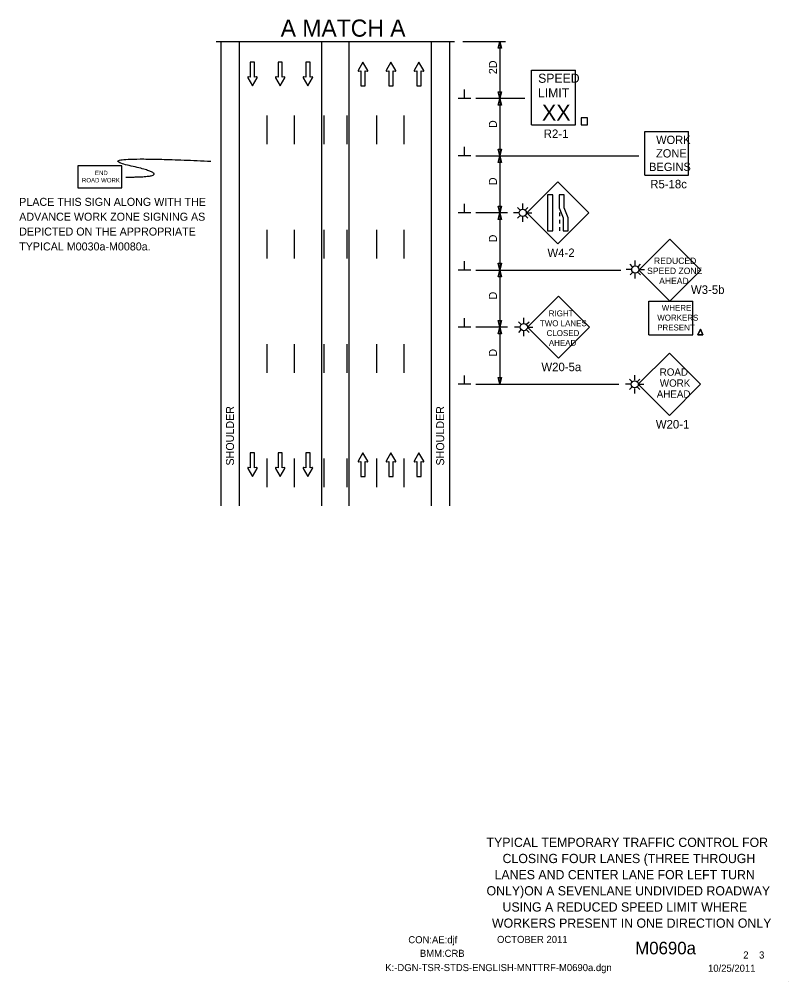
# Model space of a CAD drawing. Extents: x 16038 to 19504, y 5710 to 8321.
# Drawn here: x 17779 to 18453, y 5924 to 6766 of the extents above; entities that cross this region are included whole.
import ezdxf

# ---------------------------------------------------------------- set-up
doc = ezdxf.new("R2010")
doc.units = 0
for name, color, linetype in [('ALI_LEGAL_EX', 7, 'Continuous'), ('BORDER', 7, 'Continuous'), ('BORDER_SIGNAL_WO', 7, 'Continuous'), ('MT_SCRATCH_LEVEL_E', 7, 'Continuous'), ('PAVT_EDGE_EX', 7, 'Continuous'), ('TRAFFIC_SIGNS_PR', 7, 'Continuous'), ('TYPICAL_TEXT_DIMEN_PR', 7, 'Continuous')]:
    doc.layers.add(name, color=color, linetype=linetype)

msp = doc.modelspace()

# ---------------------------------------------------------------- linework, layer by layer
at = {"layer": 'ALI_LEGAL_EX'}
for points in [[(17995.77, 6682.18), (17995.77, 6657.18)], [(18019.77, 6682.18), (18019.77, 6657.18)], [(18045.77, 6682.18), (18045.77, 6657.18)], [(18065.77, 6682.18), (18065.77, 6657.18)], [(18091.77, 6682.18), (18091.77, 6657.18)], [(18115.77, 6682.18), (18115.77, 6657.18)], [(17995.77, 6582.18), (17995.77, 6557.18)], [(18019.77, 6582.18), (18019.77, 6557.18)], [(18045.77, 6582.18), (18045.77, 6557.18)], [(18065.77, 6582.18), (18065.77, 6557.18)], [(18091.77, 6582.18), (18091.77, 6557.18)], [(18115.77, 6582.18), (18115.77, 6557.18)], [(17995.77, 6482.18), (17995.77, 6457.18)], [(18019.77, 6482.18), (18019.77, 6457.18)], [(18045.77, 6482.18), (18045.77, 6457.18)], [(18065.77, 6482.18), (18065.77, 6457.18)], [(18091.77, 6482.18), (18091.77, 6457.18)], [(18115.77, 6482.18), (18115.77, 6457.18)], [(17995.77, 6382.18), (17995.77, 6357.18)], [(18019.77, 6382.18), (18019.77, 6357.18)], [(18045.77, 6382.18), (18045.77, 6357.18)], [(18065.77, 6382.18), (18065.77, 6357.18)], [(18091.77, 6382.18), (18091.77, 6357.18)], [(18115.77, 6382.18), (18115.77, 6357.18)]]:
    msp.add_lwpolyline(points, dxfattribs=at)
at = {"layer": 'BORDER'}
for p, q in [((18318.25, 6011.25), (18318.25, 6011.25)), ((18452.55, 5924.4), (18452.55, 5924.4))]:
    msp.add_line(p, q, dxfattribs=at)
at = {"layer": 'MT_SCRATCH_LEVEL_E'}
for p, q in [((17985.18, 6728.89), (17981.44, 6728.89)), ((17981.44, 6728.89), (17981.44, 6715.63)), ((17985.18, 6728.89), (17981.44, 6728.89)), ((17981.44, 6728.89), (17981.44, 6715.63)), ((17985.18, 6715.63), (17985.18, 6728.89)), ((17985.18, 6715.63), (17985.18, 6728.89)), ((18009.44, 6728.89), (18005.69, 6728.89)), ((18005.69, 6728.89), (18005.69, 6715.63)), ((18009.44, 6728.89), (18005.69, 6728.89)), ((18005.69, 6728.89), (18005.69, 6715.63)), ((18009.44, 6715.63), (18009.44, 6728.89)), ((18009.44, 6715.63), (18009.44, 6728.89)), ((18033.69, 6728.89), (18029.95, 6728.89)), ((18029.95, 6728.89), (18029.95, 6715.63)), ((18033.69, 6728.89), (18029.95, 6728.89)), ((18029.95, 6728.89), (18029.95, 6715.63)), ((18033.69, 6715.63), (18033.69, 6728.89)), ((18033.69, 6715.63), (18033.69, 6728.89)), ((18080.01, 6728.89), (18075.9, 6721.65)), ((18080.01, 6728.89), (18075.9, 6721.65)), ((18084.16, 6721.65), (18080.01, 6728.89)), ((18084.16, 6721.65), (18080.01, 6728.89)), ((18104.51, 6728.89), (18100.4, 6721.65)), ((18104.51, 6728.89), (18100.4, 6721.65)), ((18108.65, 6721.65), (18104.51, 6728.89)), ((18108.65, 6721.65), (18104.51, 6728.89)), ((18129, 6728.89), (18124.89, 6721.65)), ((18129, 6728.89), (18124.89, 6721.65)), ((18133.15, 6721.65), (18129, 6728.89)), ((18133.15, 6721.65), (18129, 6728.89)), ((18076.38, 6720.96), (18078.16, 6721.28)), ((18076.38, 6720.96), (18078.16, 6721.28)), ((18078.16, 6721.28), (18078.16, 6708.02)), ((18078.16, 6721.28), (18078.16, 6708.02)), ((18081.9, 6708.02), (18081.9, 6721.28)), ((18081.9, 6721.28), (18083.68, 6720.96)), ((18081.9, 6708.02), (18081.9, 6721.28)), ((18081.9, 6721.28), (18083.68, 6720.96)), ((18100.88, 6720.96), (18102.65, 6721.28)), ((18100.88, 6720.96), (18102.65, 6721.28)), ((18102.65, 6721.28), (18102.65, 6708.02)), ((18102.65, 6721.28), (18102.65, 6708.02)), ((18106.4, 6708.02), (18106.4, 6721.28)), ((18106.4, 6721.28), (18108.17, 6720.96)), ((18106.4, 6708.02), (18106.4, 6721.28)), ((18106.4, 6721.28), (18108.17, 6720.96)), ((18125.37, 6720.96), (18127.15, 6721.28)), ((18125.37, 6720.96), (18127.15, 6721.28)), ((18127.15, 6721.28), (18127.15, 6708.02)), ((18127.15, 6721.28), (18127.15, 6708.02)), ((18130.89, 6708.02), (18130.89, 6721.28)), ((18130.89, 6721.28), (18132.67, 6720.96)), ((18130.89, 6708.02), (18130.89, 6721.28)), ((18130.89, 6721.28), (18132.67, 6720.96)), ((17979.18, 6715.26), (17983.33, 6708.02)), ((17979.18, 6715.26), (17983.33, 6708.02)), ((17981.44, 6715.63), (17979.66, 6715.95)), ((17981.44, 6715.63), (17979.66, 6715.95)), ((17983.33, 6708.02), (17987.44, 6715.26)), ((17983.33, 6708.02), (17987.44, 6715.26)), ((17986.96, 6715.95), (17985.18, 6715.63)), ((17986.96, 6715.95), (17985.18, 6715.63)), ((18003.44, 6715.26), (18007.58, 6708.02)), ((18003.44, 6715.26), (18007.58, 6708.02)), ((18005.69, 6715.63), (18003.92, 6715.95)), ((18005.69, 6715.63), (18003.92, 6715.95)), ((18007.58, 6708.02), (18011.69, 6715.26)), ((18007.58, 6708.02), (18011.69, 6715.26)), ((18011.21, 6715.95), (18009.44, 6715.63)), ((18011.21, 6715.95), (18009.44, 6715.63)), ((18027.69, 6715.26), (18031.84, 6708.02)), ((18027.69, 6715.26), (18031.84, 6708.02)), ((18029.95, 6715.63), (18028.17, 6715.95)), ((18029.95, 6715.63), (18028.17, 6715.95)), ((18031.84, 6708.02), (18035.95, 6715.26)), ((18031.84, 6708.02), (18035.95, 6715.26)), ((18035.47, 6715.95), (18033.69, 6715.63)), ((18035.47, 6715.95), (18033.69, 6715.63)), ((18078.16, 6708.02), (18081.9, 6708.02)), ((18078.16, 6708.02), (18081.9, 6708.02)), ((18102.65, 6708.02), (18106.4, 6708.02)), ((18102.65, 6708.02), (18106.4, 6708.02)), ((18127.15, 6708.02), (18130.89, 6708.02)), ((18127.15, 6708.02), (18130.89, 6708.02)), ((17985.18, 6387.14), (17981.44, 6387.14)), ((17981.44, 6387.14), (17981.44, 6373.88)), ((17985.18, 6387.14), (17981.44, 6387.14)), ((17981.44, 6387.14), (17981.44, 6373.88)), ((17985.18, 6373.88), (17985.18, 6387.14)), ((17985.18, 6373.88), (17985.18, 6387.14)), ((18009.44, 6387.14), (18005.69, 6387.14)), ((18005.69, 6387.14), (18005.69, 6373.88)), ((18009.44, 6387.14), (18005.69, 6387.14)), ((18005.69, 6387.14), (18005.69, 6373.88)), ((18009.44, 6373.88), (18009.44, 6387.14)), ((18009.44, 6373.88), (18009.44, 6387.14)), ((18033.69, 6387.14), (18029.95, 6387.14)), ((18029.95, 6387.14), (18029.95, 6373.88)), ((18033.69, 6387.14), (18029.95, 6387.14)), ((18029.95, 6387.14), (18029.95, 6373.88)), ((18033.69, 6373.88), (18033.69, 6387.14)), ((18033.69, 6373.88), (18033.69, 6387.14)), ((18080.01, 6387.14), (18075.9, 6379.9)), ((18080.01, 6387.14), (18075.9, 6379.9)), ((18084.16, 6379.9), (18080.01, 6387.14)), ((18084.16, 6379.9), (18080.01, 6387.14)), ((18104.51, 6387.14), (18100.4, 6379.9)), ((18104.51, 6387.14), (18100.4, 6379.9)), ((18108.65, 6379.9), (18104.51, 6387.14)), ((18108.65, 6379.9), (18104.51, 6387.14)), ((18129, 6387.14), (18124.89, 6379.9)), ((18129, 6387.14), (18124.89, 6379.9)), ((18133.15, 6379.9), (18129, 6387.14)), ((18133.15, 6379.9), (18129, 6387.14)), ((17981.44, 6373.88), (17979.66, 6374.2)), ((17981.44, 6373.88), (17979.66, 6374.2)), ((17986.96, 6374.2), (17985.18, 6373.88)), ((17986.96, 6374.2), (17985.18, 6373.88)), ((18005.69, 6373.88), (18003.92, 6374.2)), ((18005.69, 6373.88), (18003.92, 6374.2)), ((18011.21, 6374.2), (18009.44, 6373.88)), ((18011.21, 6374.2), (18009.44, 6373.88)), ((18029.95, 6373.88), (18028.17, 6374.2)), ((18029.95, 6373.88), (18028.17, 6374.2)), ((18035.47, 6374.2), (18033.69, 6373.88)), ((18035.47, 6374.2), (18033.69, 6373.88)), ((18076.38, 6379.22), (18078.16, 6379.53)), ((18076.38, 6379.22), (18078.16, 6379.53)), ((18078.16, 6379.53), (18078.16, 6366.27)), ((18078.16, 6379.53), (18078.16, 6366.27)), ((18081.9, 6366.27), (18081.9, 6379.53)), ((18081.9, 6379.53), (18083.68, 6379.22)), ((18081.9, 6366.27), (18081.9, 6379.53)), ((18081.9, 6379.53), (18083.68, 6379.22)), ((18100.88, 6379.22), (18102.65, 6379.53)), ((18100.88, 6379.22), (18102.65, 6379.53)), ((18102.65, 6379.53), (18102.65, 6366.27)), ((18102.65, 6379.53), (18102.65, 6366.27)), ((18106.4, 6366.27), (18106.4, 6379.53)), ((18106.4, 6379.53), (18108.17, 6379.22)), ((18106.4, 6366.27), (18106.4, 6379.53)), ((18106.4, 6379.53), (18108.17, 6379.22)), ((18125.37, 6379.22), (18127.15, 6379.53)), ((18125.37, 6379.22), (18127.15, 6379.53)), ((18127.15, 6379.53), (18127.15, 6366.27)), ((18127.15, 6379.53), (18127.15, 6366.27)), ((18130.89, 6366.27), (18130.89, 6379.53)), ((18130.89, 6379.53), (18132.67, 6379.22)), ((18130.89, 6366.27), (18130.89, 6379.53)), ((18130.89, 6379.53), (18132.67, 6379.22)), ((17979.18, 6373.51), (17983.33, 6366.27)), ((17979.18, 6373.51), (17983.33, 6366.27)), ((17983.33, 6366.27), (17987.44, 6373.51)), ((17983.33, 6366.27), (17987.44, 6373.51)), ((18003.44, 6373.51), (18007.58, 6366.27)), ((18003.44, 6373.51), (18007.58, 6366.27)), ((18007.58, 6366.27), (18011.69, 6373.51)), ((18007.58, 6366.27), (18011.69, 6373.51)), ((18027.69, 6373.51), (18031.84, 6366.27)), ((18027.69, 6373.51), (18031.84, 6366.27)), ((18031.84, 6366.27), (18035.95, 6373.51)), ((18031.84, 6366.27), (18035.95, 6373.51)), ((18078.16, 6366.27), (18081.9, 6366.27)), ((18078.16, 6366.27), (18081.9, 6366.27)), ((18102.65, 6366.27), (18106.4, 6366.27)), ((18102.65, 6366.27), (18106.4, 6366.27)), ((18127.15, 6366.27), (18130.89, 6366.27)), ((18127.15, 6366.27), (18130.89, 6366.27))]:
    msp.add_line(p, q, dxfattribs=at)
for centre, start, end in [((18076.31, 6721.42), 150.42484, 279.96381), ((18076.31, 6721.42), 150.42484, 279.96381), ((18083.75, 6721.42), 260.03619, 29.77312), ((18083.75, 6721.42), 260.03619, 29.77312), ((18100.8, 6721.42), 150.42484, 279.96381), ((18100.8, 6721.42), 150.42484, 279.96381), ((18108.24, 6721.42), 260.03619, 29.77312), ((18108.24, 6721.42), 260.03619, 29.77312), ((18125.3, 6721.42), 150.42484, 279.96381), ((18125.3, 6721.42), 150.42484, 279.96381), ((18132.74, 6721.42), 260.03619, 29.77312), ((18132.74, 6721.42), 260.03619, 29.77312), ((17979.59, 6715.49), 80.03619, 209.77312), ((17979.59, 6715.49), 80.03619, 209.77312), ((17987.03, 6715.49), 330.42484, 99.96381), ((17987.03, 6715.49), 330.42484, 99.96381), ((18003.85, 6715.49), 80.03619, 209.77312), ((18003.85, 6715.49), 80.03619, 209.77312), ((18011.29, 6715.49), 330.42484, 99.96381), ((18011.29, 6715.49), 330.42484, 99.96381), ((18028.1, 6715.49), 80.03619, 209.77312), ((18028.1, 6715.49), 80.03619, 209.77312), ((18035.54, 6715.49), 330.42484, 99.96381), ((18035.54, 6715.49), 330.42484, 99.96381), ((17979.59, 6373.74), 80.03619, 209.77312), ((17979.59, 6373.74), 80.03619, 209.77312), ((17987.03, 6373.74), 330.42484, 99.96381), ((17987.03, 6373.74), 330.42484, 99.96381), ((18003.85, 6373.74), 80.03619, 209.77312), ((18003.85, 6373.74), 80.03619, 209.77312), ((18011.29, 6373.74), 330.42484, 99.96381), ((18011.29, 6373.74), 330.42484, 99.96381), ((18028.1, 6373.74), 80.03619, 209.77312), ((18028.1, 6373.74), 80.03619, 209.77312), ((18035.54, 6373.74), 330.42484, 99.96381), ((18035.54, 6373.74), 330.42484, 99.96381), ((18076.31, 6379.67), 150.42484, 279.96381), ((18076.31, 6379.67), 150.42484, 279.96381), ((18083.75, 6379.67), 260.03619, 29.77312), ((18083.75, 6379.67), 260.03619, 29.77312), ((18100.8, 6379.67), 150.42484, 279.96381), ((18100.8, 6379.67), 150.42484, 279.96381), ((18108.24, 6379.67), 260.03619, 29.77312), ((18108.24, 6379.67), 260.03619, 29.77312), ((18125.3, 6379.67), 150.42484, 279.96381), ((18125.3, 6379.67), 150.42484, 279.96381), ((18132.74, 6379.67), 260.03619, 29.77312), ((18132.74, 6379.67), 260.03619, 29.77312)]:
    msp.add_arc(centre, 0.463, start, end, dxfattribs=at)
at = {"layer": 'PAVT_EDGE_EX'}
for p, q in [((17955.77, 6747.01), (17955.77, 6340.84)), ((17971.77, 6747.01), (17971.77, 6340.84)), ((18043.77, 6747.01), (18043.77, 6340.84)), ((18067.77, 6747.01), (18067.77, 6340.84)), ((18139.77, 6747.01), (18139.77, 6340.84)), ((18155.77, 6747.01), (18155.77, 6340.84))]:
    msp.add_line(p, q, dxfattribs=at)
at = {"layer": 'TRAFFIC_SIGNS_PR'}
for p, q in [((18227.51, 6721.93), (18265.91, 6721.93)), ((18227.51, 6673.93), (18227.51, 6721.93)), ((18265.91, 6673.93), (18265.91, 6721.93)), ((18227.51, 6673.93), (18265.91, 6673.93)), ((18326.56, 6629.9), (18326.56, 6668.3)), ((18326.56, 6668.3), (18364.96, 6668.3)), ((18364.96, 6629.9), (18364.96, 6668.3)), ((18326.56, 6629.9), (18364.96, 6629.9)), ((18250.45, 6624.09), (18223.3, 6596.94)), ((18277.61, 6596.94), (18250.45, 6624.09)), ((18217.23, 6599.58), (18215.13, 6601.69)), ((18219.75, 6600.62), (18219.75, 6605.12)), ((18222.26, 6599.58), (18224.37, 6601.69)), ((18216.59, 6597.06), (18211.76, 6597.06)), ((18217.23, 6594.55), (18215.13, 6592.44)), ((18219.75, 6589.1), (18219.75, 6593.51)), ((18222.26, 6594.55), (18224.37, 6592.44)), ((18222.9, 6597.06), (18227.78, 6597.06)), ((18223.3, 6596.94), (18250.45, 6569.78)), ((18250.45, 6569.78), (18277.61, 6596.94)), ((18252.1, 6597.43), (18252.1, 6594.23)), ((18252.1, 6591.03), (18252.1, 6587.83)), ((18252.1, 6584.63), (18252.1, 6581.43)), ((18348.56, 6574.11), (18321.41, 6546.95)), ((18375.71, 6546.95), (18348.56, 6574.11)), ((18315.77, 6549.93), (18313.66, 6552.04)), ((18318.28, 6550.97), (18318.28, 6555.48)), ((18320.8, 6549.93), (18322.9, 6552.04)), ((18315.13, 6547.42), (18310.29, 6547.42)), ((18315.77, 6544.91), (18313.66, 6542.8)), ((18318.28, 6539.45), (18318.28, 6543.86)), ((18320.8, 6544.91), (18322.9, 6542.8)), ((18321.41, 6546.95), (18348.56, 6519.8)), ((18321.44, 6547.42), (18326.32, 6547.42)), ((18348.56, 6519.8), (18375.71, 6546.95)), ((18250.98, 6524.24), (18223.83, 6497.09)), ((18278.14, 6497.09), (18250.98, 6524.24)), ((18330.11, 6519.64), (18368.51, 6519.64)), ((18330.11, 6490.32), (18330.11, 6519.64)), ((18368.51, 6490.32), (18368.51, 6519.64)), ((18218.16, 6499.61), (18216.06, 6501.71)), ((18220.68, 6500.65), (18220.68, 6505.15)), ((18223.19, 6499.61), (18225.3, 6501.71)), ((18217.52, 6497.09), (18212.69, 6497.09)), ((18218.16, 6494.58), (18216.06, 6492.47)), ((18220.68, 6489.13), (18220.68, 6493.54)), ((18223.19, 6494.58), (18225.3, 6492.47)), ((18223.83, 6497.09), (18228.71, 6497.09)), ((18223.83, 6497.09), (18250.98, 6469.94)), ((18250.98, 6469.94), (18278.14, 6497.09)), ((18330.11, 6490.32), (18368.51, 6490.32)), ((18348.1, 6474.19), (18320.91, 6447.01)), ((18375.29, 6447.01), (18348.1, 6474.19)), ((18315.25, 6449.52), (18313.14, 6451.63)), ((18317.76, 6450.56), (18317.76, 6455.07)), ((18320.27, 6449.52), (18322.38, 6451.63)), ((18314.61, 6447.01), (18309.77, 6447.01)), ((18315.25, 6444.5), (18313.14, 6442.39)), ((18317.76, 6439.04), (18317.76, 6443.45)), ((18320.27, 6444.5), (18322.38, 6442.39)), ((18320.91, 6447.01), (18325.79, 6447.01)), ((18320.91, 6447.01), (18348.1, 6419.82)), ((18348.1, 6419.82), (18375.29, 6447.01))]:
    msp.add_line(p, q, dxfattribs=at)
for points in [[(18270.93, 6673.93), (18276.52, 6673.93), (18276.52, 6680.1), (18270.93, 6680.1)], [(17830.52, 6618.92), (17868.92, 6618.92), (17868.92, 6638.12), (17830.52, 6638.12)], [(18241.56, 6612.67), (18241.56, 6581.43), (18246.05, 6581.43), (18246.05, 6612.67)], [(18251.7, 6612.67), (18251.7, 6601.49), (18255.04, 6592.61), (18255.04, 6581.43), (18259.53, 6581.43), (18259.53, 6592.61), (18256.19, 6601.49), (18256.19, 6612.67)]]:
    msp.add_lwpolyline(points, close=True, dxfattribs=at)
for points in [[(18375.26, 6495.26), (18373.03, 6490.32)], [(18373.03, 6490.32), (18375.26, 6495.26)], [(18377.5, 6490.32), (18375.26, 6495.26)], [(18375.26, 6495.26), (18377.5, 6490.32)], [(18373.03, 6490.32), (18377.5, 6490.32)], [(18377.5, 6490.32), (18373.03, 6490.32)]]:
    msp.add_lwpolyline(points, dxfattribs=at)
for centre in [(18219.75, 6597.06), (18318.28, 6547.42), (18220.68, 6497.09), (18317.76, 6447.01)]:
    msp.add_circle(centre, 3.15, dxfattribs=at)
msp.add_open_spline([(17872.52, 6628.3), (17919.75, 6628.3), (17834.73, 6647.64), (17947.03, 6642.15)], degree=2, dxfattribs=at)
at = {"layer": 'TYPICAL_TEXT_DIMEN_PR'}
for p, q in [((17951.47, 6747.01), (18160.07, 6747.01)), ((18043.77, 6747.01), (18067.77, 6747.01)), ((18167.46, 6747.01), (18204.77, 6747.01)), ((18198.2, 6741.15), (18199.77, 6747.01)), ((18199.77, 6747.01), (18201.34, 6741.15)), ((18199.77, 6747.01), (18199.77, 6697.01)), ((18199.77, 6741.15), (18198.2, 6741.15)), ((18201.34, 6741.15), (18199.77, 6741.15)), ((18168.89, 6697.01), (18168.89, 6704.79)), ((18199.77, 6697.01), (18198.2, 6702.87)), ((18198.2, 6702.87), (18199.77, 6702.87)), ((18199.77, 6702.87), (18201.34, 6702.87)), ((18201.34, 6702.87), (18199.77, 6697.01)), ((18174.52, 6697.01), (18163.27, 6697.01)), ((18221.76, 6697.01), (18178.77, 6697.01)), ((18198.2, 6691.15), (18199.77, 6697.01)), ((18199.77, 6697.01), (18201.34, 6691.15)), ((18199.77, 6697.01), (18199.77, 6647.01)), ((18199.77, 6691.15), (18198.2, 6691.15)), ((18201.34, 6691.15), (18199.77, 6691.15)), ((18168.89, 6647.01), (18168.89, 6654.79)), ((18199.77, 6647.01), (18198.2, 6652.87)), ((18198.2, 6652.87), (18199.77, 6652.87)), ((18199.77, 6652.87), (18201.34, 6652.87)), ((18201.34, 6652.87), (18199.77, 6647.01)), ((18174.52, 6647.01), (18163.27, 6647.01)), ((18178.77, 6647.01), (18321.42, 6647.01)), ((18198.2, 6641.15), (18199.77, 6647.01)), ((18199.77, 6647.01), (18199.77, 6597.01)), ((18199.77, 6647.01), (18201.34, 6641.15)), ((18199.77, 6641.15), (18198.2, 6641.15)), ((18201.34, 6641.15), (18199.77, 6641.15)), ((18168.89, 6597.01), (18168.89, 6604.79)), ((18199.77, 6597.01), (18198.2, 6602.87)), ((18198.2, 6602.87), (18199.77, 6602.87)), ((18199.77, 6602.87), (18201.34, 6602.87)), ((18201.34, 6602.87), (18199.77, 6597.01)), ((18174.52, 6597.01), (18163.27, 6597.01)), ((18206.44, 6597.01), (18178.77, 6597.01)), ((18198.2, 6591.15), (18199.77, 6597.01)), ((18199.77, 6597.01), (18201.34, 6591.15)), ((18199.77, 6597.01), (18199.77, 6547.01)), ((18199.77, 6591.15), (18198.2, 6591.15)), ((18201.34, 6591.15), (18199.77, 6591.15)), ((18168.89, 6547.01), (18168.89, 6554.79)), ((18199.77, 6547.01), (18198.2, 6552.87)), ((18198.2, 6552.87), (18199.77, 6552.87)), ((18199.77, 6552.87), (18201.34, 6552.87)), ((18201.34, 6552.87), (18199.77, 6547.01)), ((18174.52, 6547.01), (18163.27, 6547.01)), ((18178.77, 6547.01), (18305.65, 6547.01)), ((18198.2, 6541.15), (18199.77, 6547.01)), ((18199.77, 6547.01), (18201.34, 6541.15)), ((18199.77, 6547.01), (18199.77, 6497.01)), ((18199.77, 6541.15), (18198.2, 6541.15)), ((18201.34, 6541.15), (18199.77, 6541.15)), ((18168.89, 6497.01), (18168.89, 6504.79)), ((18199.77, 6497.01), (18198.2, 6502.87)), ((18198.2, 6502.87), (18199.77, 6502.87)), ((18199.77, 6502.87), (18201.34, 6502.87)), ((18201.34, 6502.87), (18199.77, 6497.01)), ((18174.52, 6497.01), (18163.27, 6497.01)), ((18206.44, 6497.01), (18178.77, 6497.01)), ((18198.2, 6491.15), (18199.77, 6497.01)), ((18199.77, 6497.01), (18201.34, 6491.15)), ((18199.77, 6497.01), (18199.77, 6447.01)), ((18199.77, 6491.15), (18198.2, 6491.15)), ((18201.34, 6491.15), (18199.77, 6491.15)), ((18168.89, 6447.01), (18168.89, 6454.79)), ((18199.77, 6447.01), (18198.2, 6452.87)), ((18198.2, 6452.87), (18199.77, 6452.87)), ((18199.77, 6452.87), (18201.34, 6452.87)), ((18201.34, 6452.87), (18199.77, 6447.01)), ((18174.52, 6447.01), (18163.27, 6447.01)), ((18178.77, 6447.01), (18303.77, 6447.01))]:
    msp.add_line(p, q, dxfattribs=at)

# ---------------------------------------------------------------- texts
at = {"layer": 'BORDER'}
for s, p in [('TYPICAL TEMPORARY TRAFFIC CONTROL FOR ', (18188.13, 6042.33)), ('CLOSING FOUR LANES (THREE THROUGH ', (18202.13, 6028.2)), ('LANES AND CENTER LANE FOR LEFT TURN ', (18195.13, 6014.06)), ('ONLY)ON A SEVENLANE UNDIVIDED ROADWAY ', (18188.13, 5999.92)), ('USING A REDUCED SPEED LIMIT WHERE ', (18202.13, 5985.79)), ('WORKERS PRESENT IN ONE DIRECTION ONLY', (18192.87, 5971.65))]:
    msp.add_text(s, height=8.066, dxfattribs=at).set_placement(p)
at = {"layer": 'BORDER_SIGNAL_WO'}
for s, height, p in [('CON:AE:djf', 6.2, (18119.69, 5958.06)), ('    OCTOBER 2011    ', 6.2, (18188.08, 5958.34)), ('    M0690a   ', 11, (18301.86, 5948.38)), ('BMM:CRB   ', 6.2, (18129.81, 5946.17)), (' 2    3 ', 6.2, (18410.45, 5944.7)), ('K:-DGN-TSR-STDS-ENGLISH-MNTTRF-M0690a.dgn        ', 6.2, (18099.55, 5933.71)), ('10/25/2011    ', 6.2, (18381.93, 5933.13))]:
    msp.add_text(s, height=height, dxfattribs=at).set_placement(p)
at = {"layer": 'TRAFFIC_SIGNS_PR'}
for s, height, p in [('SPEED', 8, (18233.28, 6710.79)), ('LIMIT', 8, (18233.12, 6697.99)), ('XX', 14.031, (18236.62, 6677.68)), ('R2-1', 7.44, (18238.19, 6662.49)), ('WORK', 7.217, (18336.56, 6657.27)), ('ZONE', 7.217, (18336.44, 6645.46)), ('BEGINS', 7.217, (18330.37, 6633.65)), ('ROAD WORK', 3.831, (17834.13, 6623.66)), ('END', 3.831, (17845.53, 6630.05)), ('R5-18c', 7.44, (18331.37, 6618.46)), ('PLACE THIS SIGN ALONG WITH THE', 7, (17779.24, 6603.14)), ('ADVANCE WORK ZONE SIGNING AS', 7, (17779.24, 6590.14)), ('DEPICTED ON THE APPROPRIATE', 7, (17779.24, 6577.14)), ('TYPICAL M0030a-M0080a.', 7, (17779.24, 6564.14)), ('W4-2', 7.44, (18241.41, 6558.34)), ('REDUCED', 5.6, (18334.62, 6552.26)), ('SPEED ZONE', 5.6, (18328.61, 6543.46)), ('AHEAD', 5.6, (18339.17, 6534.66)), ('W3-5b', 7.44, (18366.99, 6526.13)), ('RIGHT', 5.2, (18242.56, 6506.43)), ('WHERE', 5.2, (18341.43, 6511.32)), ('TWO LANES', 5.2, (18234.84, 6497.83)), ('WORKERS', 5.2, (18337.5, 6502.72)), ('CLOSED', 5.2, (18240.69, 6489.23)), ('PRESENT', 5.2, (18337.43, 6494.12)), ('AHEAD', 5.2, (18242.64, 6480.63)), ('W20-5a', 7.44, (18236.12, 6458.5)), ('ROAD', 6.408, (18339.63, 6454.55)), ('WORK', 6.408, (18339.74, 6444.94)), ('AHEAD', 6.408, (18337.05, 6435.33)), ('W20-1', 7.449, (18336.26, 6408.37))]:
    msp.add_text(s, height=height, dxfattribs=at).set_placement(p)
at = {"layer": 'TYPICAL_TEXT_DIMEN_PR'}
msp.add_text('A MATCH A', height=15, dxfattribs=at).set_placement((18008.01, 6751.15))
for s, p in [('2D', (18197.21, 6718.35)), ('D', (18197.21, 6671.23)), ('D', (18197.21, 6621.23)), ('D', (18197.21, 6571.23)), ('D', (18197.21, 6521.23)), ('D', (18197.21, 6471.23)), ('SHOULDER', (17967.14, 6375.99)), ('SHOULDER', (18151.05, 6375.99))]:
    msp.add_text(s, height=7, rotation=90, dxfattribs=at).set_placement(p)

doc.saveas('drawing.dxf')
